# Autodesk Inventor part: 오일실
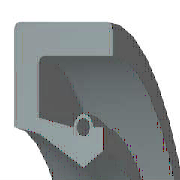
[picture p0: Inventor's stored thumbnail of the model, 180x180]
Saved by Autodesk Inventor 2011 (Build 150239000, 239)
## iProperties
IsCustomPart: 1
Created: 2009-02
Part Number: 오일실
Material: 고무
Description: 오일-실
Document SubType Name: Modeling
Standard: KS B 2804
Designer: SeoGD™[esajin.kr]
Standards Organization: KS
Language: ko-KR
Size Designation: S - 25 38 8
Categories: <MemberInstance><Categories><Category DisplayName="샤프트 부품" InternalName="7f7aeb1f-a693-4053-b835-cee3144e0d98" Mnemonic="SHFT"><Category DisplayName="실링" Intern
Density: 0.93 g/cm^3
Author: SeoGD™[esajin.kr]
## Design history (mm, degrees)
revolve "본체" stored, may be unused: angle "d17" = 90 deg
revolve "스프링1" stored, may be unused: angle "d18" = 90 deg
body "Solid1"
sketch "스케치1"
  geometry: L1 (0, 19)-(8, 19); L2 (8, 19)-(8, 17.75); L3 (8, 17.75)-(1.75, 17.75); L4 (0, 19)-(0, 14.6); L5 (0, 14.6)-(1.75, 14.25); L6 (1.75, 14.25)-(4.9, 12.5); L7 (4.9, 12.5)-(0, 12.5); L8 (6.3, 13.375)-(6.3, 14.6); L9 (0, 0)-(9.586, 0) reference; L10 (4.9, 12.5)-(6.3, 13.375); L11 (0, 18)-(0, -3) reference; L12 (-1.917, 0)-(11.503, 0) reference; L13 (4.2, 14.6)-(1.75, 15.09); L14 (1.75, 15.09)-(1.75, 17.75); L15 (6.3, 14.6)-(5.6, 14.6); C1 r 0.455 at (4.9, 14.6); A1 r 0.7 centre (4.9, 14.6) between (5.6, 14.6) and (4.2, 14.6)
  constraints: 26 end point, 5 horizontal alignment, 4 perpendicular, 2 centre point, 2 collinear, 2 horizontal, 2 parallel, 2 point on circle, 2 point on line, 2 vertical alignment, 1 coincident
  dimensions: "d0" = 38 diameter of L1 L9 (= SD2); "d1" = 26.75 diameter of L8.start L9 (= ABDM); "d2" = 1.25 distance of L1.end L2.end (computed from SD); "d3" = 0.91 diameter of C1 (= SPDI); "d4" = 1.4 diameter of A1 (= SPDA); "d5" = 25 diameter of L6.end L9 (= NND); "d6" = 28.5 diameter of L5.end L9 (= TKDM); "d7" = 29.2 diameter of L4.end L9 (= HLDM); "d8" = 4.9 distance from line of C1.centre L4 (= SPDST); "d9" = 6.3 distance between parallel lines of L8 L4 (= SDI); "d10" = 8 distance between parallel lines of L2 L4 (= SWDT); "d12" = 1.75 distance between parallel lines of L14 L4 (= SD)
fillet "모깎기1" dims "d11" = 0.3 (= RR)
other parameters: "SD2" = 38 [user parameter; used in 1 equation term], "SWDT" = 8 [user parameter; used in 1 equation term], "RR" = 0.3 [user parameter; used in 1 equation term], "SD" = 1.75 [user parameter; used in 2 equation terms], "NND" = 25 [user parameter; used in 1 equation term], "SPDA" = 1.4 [user parameter; used in 1 equation term], "SPDI" = 0.91 [user parameter; used in 1 equation term], "TKDM" = 28.5 [user parameter; used in 1 equation term], "HLDM" = 29.2 [user parameter; used in 1 equation term], "ABDM" = 26.75 [user parameter; used in 1 equation term], "SDI" = 6.3 [user parameter; used in 1 equation term], "SPDST" = 4.9 [user parameter; used in 1 equation term], "d13" = 0, "d14" = 0, "d15" = 0, "LAB" = 0.35 [user parameter]
